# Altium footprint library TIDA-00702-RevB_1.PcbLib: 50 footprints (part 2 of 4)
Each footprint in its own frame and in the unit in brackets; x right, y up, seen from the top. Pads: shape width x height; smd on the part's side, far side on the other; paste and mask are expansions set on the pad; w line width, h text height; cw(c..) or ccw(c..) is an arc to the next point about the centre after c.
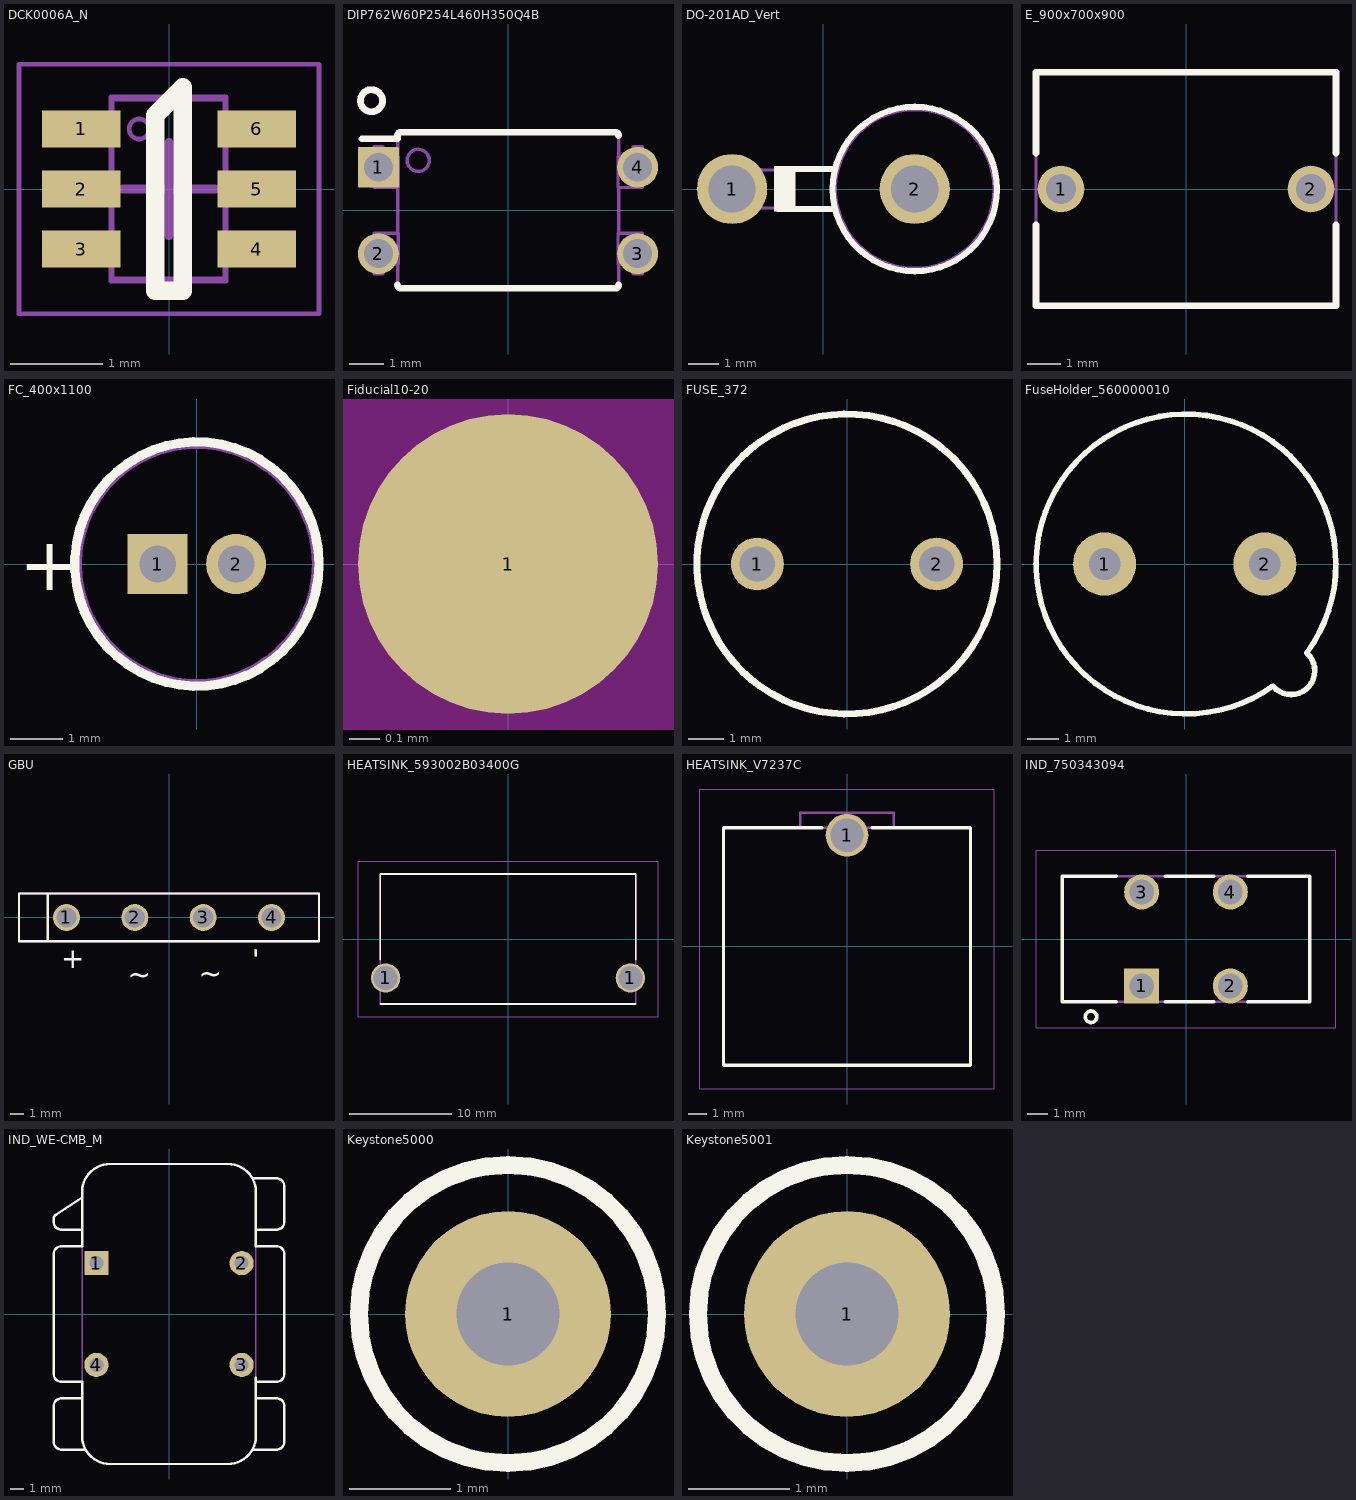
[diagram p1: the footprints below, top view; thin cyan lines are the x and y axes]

## DCK0006A_N [mm] "SOT23, 6-Leads, Body 2x1.3mm, Pitch 0.65mm, Lead Span 2.1mm, IPC Medium Density"
height 1.1
pads (6):
  rect 0.85x0.4 smd: 1(-0.95,0.65) 2(-0.95,0) 3(-0.95,-0.65) 4(0.95,-0.65) 5(0.95,0) 6(0.95,0.65)
Top Overlay:
  lines w0.2: -0.15,-1.1 -0.15,0.8 0.15,1.1 0.15,-1.1 -0.15,-1.1
Mechanical 5:
  lines w0.05: -0.613,-0.763 -0.613,-0.976 0.607,-0.976 0.607,-0.763 ; -0.613,-0.538 -0.613,-0.113 ; -0.613,0.112 -0.613,0.537 ; -0.613,0.762 -0.613,0.974 0.607,0.974 0.607,0.762 ; 0.607,-0.538 0.607,-0.113 ; 0.607,0.112 0.607,0.537 ; -0.628,-0.763 -0.628,-1.001 0.622,-1.001 0.622,-0.763 ; -0.628,-0.763 -0.853,-0.763 -0.865,-0.763 -0.959,-0.763 -1.143,-0.763 -1.143,-0.538 -0.959,-0.538 -0.865,-0.538 -0.853,-0.538 -0.628,-0.538 ; -0.628,-0.763 -0.591,-0.763 -0.591,-0.538 -0.628,-0.538 ; -0.628,-0.538 -0.628,-0.113 ; -0.628,-0.113 -0.853,-0.113 -0.865,-0.113 -0.959,-0.113 -1.143,-0.113 -1.143,0.112 -0.959,0.112 -0.865,0.112 -0.853,0.112 -0.628,0.112 ; -0.628,-0.113 -0.591,-0.113 -0.591,0.112 -0.628,0.112 ; -0.628,0.112 -0.628,0.537 ; -0.628,0.537 -0.853,0.537 -0.865,0.537 -0.959,0.537 -1.143,0.537 -1.143,0.762 -0.959,0.762 -0.865,0.762 -0.853,0.762 -0.628,0.762 ; -0.628,0.537 -0.591,0.537 -0.591,0.762 -0.628,0.762 ; -0.628,0.762 -0.628,0.999 0.622,0.999 0.622,0.762 ; 0.622,-0.763 0.847,-0.763 0.859,-0.763 0.953,-0.763 1.137,-0.763 1.137,-0.538 0.953,-0.538 0.859,-0.538 0.847,-0.538 0.622,-0.538 ; 0.622,-0.763 0.585,-0.763 0.585,-0.538 0.622,-0.538 ; 0.622,-0.538 0.622,-0.113 ; 0.622,-0.113 0.585,-0.113 0.585,0.112 0.622,0.112 ; 0.622,-0.113 0.847,-0.113 0.859,-0.113 0.953,-0.113 1.137,-0.113 1.137,0.112 0.953,0.112 0.859,0.112 0.847,0.112 0.622,0.112 ; 0.622,0.112 0.622,0.537 ; 0.622,0.537 0.847,0.537 0.859,0.537 0.953,0.537 1.137,0.537 1.137,0.762 0.953,0.762 0.859,0.762 0.847,0.762 0.622,0.762 ; 0.622,0.537 0.585,0.537 0.585,0.762 0.622,0.762 ; -0.432,0.65 cw(c-0.323,0.65) -0.215,0.65 cw(c-0.323,0.65) -0.432,0.65
  text ".Designator" at -1.524,-0.584 h0.89
Mechanical 15:
  lines w0.05: -1.625,-1.35 -1.625,1.35 1.625,1.35 1.625,-1.35 -1.625,-1.35
  lines w0.1: -0.5,0 0.5,0 ; 0,-0.5 0,0.5
3D body: height 0.94, standoff -0.01, extent -1.14,-1 1.14,1

## DIP762W60P254L460H350Q4B [mm] "LITE-ON"
height 4.5
pads (4):
  rrect8% 1.2x1.2 hole 0.85: 1(-3.81,1.27)
  round 1.2 hole 0.85: 2(-3.81,-1.27) 3(3.81,-1.27) 4(3.81,1.27)
Top Overlay:
  circle w0.2: c-4.013,3.226 r0.325
  lines w0.2: -4.293,2.108 -3.247,2.108 -3.247,2.201 cw(c-3.148,2.201) -3.148,2.3 3.154,2.3 cw(c3.154,2.201) 3.253,2.201 ; -3.247,-2.191 ccw(c-3.148,-2.192) -3.148,-2.29 3.154,-2.29 ccw(c3.154,-2.192) 3.253,-2.191
Mechanical 5:
  circle w0.1: c-2.642,1.473 r0.325
  lines w0.1: -3.677,-1.565 -3.677,-1.865 -3.937,-1.865 -3.937,-1.565 ; -3.677,1.575 -3.677,1.875 -3.937,1.875 -3.937,1.575 ; -3.247,-1.565 -3.247,-2.191 ccw(c-3.148,-2.192) -3.148,-2.29 3.154,-2.29 ccw(c3.154,-2.192) 3.253,-2.191 3.253,-1.565 ; -3.247,-0.665 -3.247,0.675 ; -3.247,1.575 -3.247,2.201 cw(c-3.148,2.201) -3.148,2.3 3.154,2.3 cw(c3.154,2.201) 3.253,2.201 3.253,1.575 ; 3.253,-0.665 3.253,0.675 ; 3.683,-1.565 3.683,-1.865 3.943,-1.865 3.943,-1.565 ; 3.683,1.575 3.683,1.875 3.943,1.875 3.943,1.575 ; -3.937,-1.565 -3.737,-1.565 -3.229,-1.565 -3.229,-0.665 -3.737,-0.665 -3.937,-0.665 -3.937,-1.565 ; -3.937,1.575 -3.737,1.575 -3.229,1.575 -3.229,0.675 -3.737,0.675 -3.937,0.675 -3.937,1.575 ; 3.943,-1.565 3.743,-1.565 3.235,-1.565 3.235,-0.665 3.743,-0.665 3.943,-0.665 3.943,-1.565 ; 3.943,1.575 3.943,0.675 3.743,0.675 3.235,0.675 3.235,1.575 3.743,1.575 3.943,1.575
  text ".Designator" at 0.406,-0.025 h0.89
3D body: height 4.3, standoff -2.7, extent -3.94,-2.295 3.94,2.295

## DO-201AD_Vert [mm] "DO-201AD VERTICAL FOOTPRINT"
height 14.5
pads (2):
  round 2.3 hole 1.55: 1(-3,0) 2(3,0)
Top Overlay:
  circle w0.2: c3,0 r2.7
  rectangle: -1.621,-0.744 -0.921,0.756
  lines w0.2: -1.5,-0.65 0.3,-0.65 ; -1.5,0.65 0.3,0.65
Mechanical 5:
  circle w0.1: c3,0 r2.6
  rectangle: -2.696,-0.655 -1.996,0.695
  lines w0.1: -3,-0.625 0.4,-0.625 ; -3,-0.6 -3,0.6 ; -2.975,0.625 0.425,0.625
  text ".Designator" at 3.277,0.127 h0.89
3D body: height 14.8, standoff -2.54, extent -3.659,-2.655 5.655,2.655

## E_900x700x900 [mm] "TH, 2- Leads, Body 9x7mm, Pin Spacing 7.5mm"
height 12
pads (2):
  round 1.4 hole 0.9: 1(-3.75,0) 2(3.75,0)
Top Overlay:
  lines w0.2: -4.5,-1.071 -4.5,-3.5 4.5,-3.5 4.5,-1.071 ; -4.5,1.071 -4.5,3.5 4.5,3.5 4.5,1.071
Mechanical 5:
  lines w0.1: -4.5,-3.5 4.5,-3.5 4.5,3.5 -4.5,3.5 -4.5,-3.5
  text ".Designator" at -1.397,-0.406 h0.89
3D body: height 0.3, standoff -2.5, extent -4.047,-0.299 -3.45,0.3
3D body: height 1.36, standoff -0.16, extent -4.047,-1.732 -3.45,0.3
3D body: height 6.12, standoff 0.81, extent -4.047,-1.732 -1.545,-1.033
3D body: height 6.12, standoff 0.81, extent 1.546,1.033 4.048,1.732
3D body: height 1.36, standoff -0.16, extent 3.45,-0.299 4.048,1.732
3D body: height 0.3, standoff -2.5, extent 3.45,-0.299 4.048,0.299
3D body: height 11.96, standoff 3, extent -4.491,-3.5 4.491,3.5

## FC_400x1100 [mm] "Panasonic"
height 12
pads (2):
  rect 1.15x1.15 hole 0.7: 1(-0.75,0)
  round 1.15 hole 0.7: 2(0.75,0)
Top Overlay:
  circle w0.18: c0,0 r2.335
  text "+" at -3.4,-0.5 h1.02
Mechanical 5:
  circle w0.1: c0,0 r2.25
  text ".Designator" at -0.483,1.168 h0.89
  text "+" at -3.4,-0.5 h0.89
3D body: height 12.01, standoff -4, extent -2.232,-2.246 2.252,2.246

## FCC_disclaimer [mm]

## Fiducial10-20 [mm]
pads (1):
  round 1 smd mask+0.5: 1(0,0)
Top Layer keep-out:
  circle w1.178: c0,0 r0.5

## FUSE_372 [mm] "LITTELFUSE"
height 8
pads (2):
  round 1.5 hole 1: 1(-2.54,0) 2(2.54,0)
Top Overlay:
  circle w0.2: c0,0 r4.25
Mechanical 5:
  circle w0.1: c0,0 r4.25
  text ".Designator" at -0.838,-0.559 h0.89
3D body: height 4, standoff -2, extent -2.837,-0.299 -2.24,0.3
3D body: height 4, standoff -2, extent 2.242,-0.299 2.84,0.299
3D body: height 8, standoff 0, extent -4.259,-4.259 4.259,4.259

## FuseHolder_560000010 [mm] "Littelfuse fuse holder TR5"
height 5.6
pads (2):
  round 2 hole 1: 1(-2.54,0) 2(2.54,0)
Top Overlay:
  lines w0.178: -4.71,-0.051 cw(c-4.212,0) -4.71,0.051 ; 4.79,-0.051 ccw(c4.292,0) 4.79,0.051 ; 2.797,-3.868 cw(c0.04,0) 3.863,-2.819 cw(c3.372,-3.386) 2.797,-3.868
Mechanical 5:
  lines w0.127: -4.71,-0.051 cw(c-4.212,0) -4.71,0.051 ; 4.79,-0.051 ccw(c4.292,0) 4.79,0.051 ; 2.797,-3.868 ccw(c3.372,-3.386) 3.863,-2.819 ccw(c0.04,0) 2.797,-3.868
  text ".Designator" at -6.807,-2.108 h0.89
3D body: height 5.6, standoff -3, extent -4.752,-4.737 4.752,4.75

## GBU [mm] "Comchip / Diodes Inc diode bridge"
height 21.55
pads (4):
  round 2 hole 1.5: 1(-7.62,0) 2(-2.54,0) 3(2.54,0) 4(7.62,0)
Top Overlay:
  lines w0.178: -9,-1.78 -9,1.78 ; -11.15,-1.78 0,-1.78 11.15,-1.78 11.15,0 11.15,1.78 0,1.78 -11.15,1.78 -11.15,0 -11.15,-1.78
  text "~" at 2.21,-4.877 h1.52
  text "~" at -3.073,-4.978 h1.52
  text "-" at 7.061,-3.048 h1.52
  text "+" at -8.026,-3.759 h1.52
Mechanical 5:
  lines w0.127: -9,-1.78 -9,1.78 ; -11.15,-1.78 0,-1.78 11.15,-1.78 11.15,0 11.15,1.78 0,1.78 -11.15,1.78 -11.15,0 -11.15,-1.78
  text "~" at 2.311,-3.226 h0.89
  text "~" at -1.676,-3.277 h0.89
  text "-" at 7.061,-2.591 h0.89
  text "+" at -7.823,-2.972 h0.89
  text ".Designator" at -0.787,1.041 h0.89
3D body: height 21.55, standoff -15.25, extent -11.15,-1.76 11.15,1.8

## HEATSINK_593002B03400G [mm] "HEATSINK, 25X12.7X29.97 MM"
height 29.97
pads (2):
  round 2.868 hole 2.36: 1(-11.965,-3.81) 1(11.965,-3.81)
Top Overlay:
  lines w0.178: -12.5,-6.35 12.5,-6.35 ; -12.5,-2 -12.5,6.35 12.5,6.35 12.5,-2
  text ".Designator" at -13.843,3.099 h0.89
Mechanical 5:
  lines w0.127: -12.5,-6.35 12.5,-6.35 12.5,6.35 -12.5,6.35 -12.5,-6.35
  text ".Designator" at 12.979,7.112 h0.89
Mechanical 15:
  lines w0.05: -14.669,-7.62 14.669,-7.62 14.669,7.62 -14.669,7.62 -14.669,-7.62
Mechanical 17:
  text "LEAD LENGTH: 4.27 MM" at -9.652,2.286 h1
3D body: height 29.97, standoff 0, extent -12.5,-6.35 12.5,6.35

## HEATSINK_V7237C [mm] "HEATSINK,TO-220,13.21X12.7MM"
height 19.05
pads (1):
  round 2.28 hole 1.78: 1(0,5.95)
Top Overlay:
  lines w0.178: -1.342,6.35 -6.605,6.35 -6.605,-6.35 6.605,-6.35 6.605,6.35 1.342,6.35
  text ".Designator" at -2.87,-7.569 h0.89
Mechanical 5:
  lines w0.127: -2.5,6.35 -2.5,7.15 2.5,7.15 2.5,6.35 ; -6.605,-6.35 6.605,-6.35 6.605,6.35 -6.605,6.35 -6.605,-6.35
  text ".Designator" at -6.248,6.756 h0.89
Mechanical 15:
  lines w0.05: -7.875,-7.62 7.875,-7.62 7.875,8.42 -7.875,8.42 -7.875,-7.62
Mechanical 17:
  text "LEAD LENGTH: 6.35 MM" at -9.169,-2.515 h1
3D body: height 19.05, standoff 0, extent -6.605,-6.35 6.605,6.35

## IND_750343094 [mm] "INDUCTOR, TH-4P"
height 13.06
pads (4):
  rect 1.7x1.7 / inner round 1.7 / far side rect 1.7x1.7 hole 1.2: 1(-2.16,-2.285)
  round 1.7 hole 1.2: 2(2.16,-2.285) 3(-2.16,2.285) 4(2.16,2.285)
Top Overlay:
  circle w0.178: c-4.623,-3.785 r0.279
  lines w0.178: -3.4,-3.05 -6.03,-3.05 -6.03,3.05 -3.4,3.05 ; -1,-3.05 1.35,-3.05 ; -1,3.05 1.35,3.05 ; 3,-3.05 6.03,-3.05 6.03,3.05 3,3.05
Bottom Overlay:
  lines w0.178: -6.03,-3.048 -5.302,-3.048 ; -6.03,-1.966 -6.03,-0.95 ; -6.03,0.034 -6.03,1.05 ; -6.03,2.034 -6.03,3.05 -4.887,3.05 ; -4.445,-3.048 -3.302,-3.048 ; -4.03,3.05 -2.92,3.05 ; -1.35,3.05 1.27,3.048 ; -1,-3.05 1.35,-3.05 ; 2.92,-3.05 4.03,-3.05 ; 3.175,3.048 4.445,3.048 ; 4.887,-3.05 6.03,-3.05 6.03,-2.034 ; 5.302,3.048 6.03,3.048 ; 6.03,-1.05 6.03,-0.034 ; 6.03,0.95 6.03,1.966
Mechanical 5:
  circle w0.127: c-2.16,-2.285 r0.279
  lines w0.127: -6.03,-3.05 6.03,-3.05 6.03,3.05 -6.03,3.05 -6.03,-3.05
  text ".Designator" at -1.524,-0.508 h0.89
Mechanical 15:
  lines w0.05: -7.3,-4.32 7.3,-4.32 7.3,4.32 -7.3,4.32 -7.3,-4.32
Mechanical 17:
  text "LEAD LENGHT: 2.81MM" at -13.843,-6.604 h1.52
3D body: height 13.06, standoff 0, extent -6.03,-3.05 6.03,3.05

## IND_WE-CMB_M [mil] "Wurth"
height 1102.36
pads (4):
  rect 70x70 hole 40: 1(-210.63,147.64)
  round 70 hole 40: 2(210.63,147.64) 3(210.63,-147.64) 4(-210.63,-147.64)
Top Overlay:
  lines w7: -251.97,-354.33 ccw(c-171.26,-354.33) -171.26,-435.04 171.26,-435.04 ccw(c171.26,-354.33) 251.97,-354.33 251.97,-346.59 251.97,-323.7 251.97,-286.66 251.97,-237.09 251.97,-184.41 ; -251.97,-354.08 -251.97,-349.11 -251.97,-328.88 -251.97,-294.28 -251.97,-246.81 -251.97,-206.08 -251.97,-203.51 -251.97,-198.82 ; -251.97,-244.09 -311.02,-244.09 ccw(c-311.02,-267.72) -334.65,-267.72 -334.65,-370.08 ccw(c-311.02,-370.08) -311.02,-393.7 -241.67,-393.7 ; -251.97,-196.85 -311.02,-196.85 cw(c-311.02,-173.23) -334.65,-173.23 -334.65,173.23 cw(c-311.02,173.23) -311.02,196.85 -251.97,196.85 ; -251.97,198.82 -251.97,203.51 -251.97,206.08 -251.97,246.81 -251.97,294.28 -251.97,328.88 -251.97,349.11 -251.97,354.08 ; -251.97,244.09 -311.02,244.09 cw(c-311.02,267.72) -334.65,267.72 -334.65,274.98 cw(c-318.9,274.98) -327.56,288.13 -251.97,337.93 ; -251.97,354.33 cw(c-171.26,354.33) -171.26,435.04 171.26,435.04 cw(c171.26,354.33) 251.97,354.33 251.97,346.59 251.97,323.7 251.97,286.66 251.97,196.85 311.02,196.85 cw(c311.02,173.23) 334.65,173.23 334.65,-173.23 cw(c311.02,-173.23) 311.02,-196.85 251.97,-196.85 ; 241.71,-393.7 311.02,-393.7 ccw(c311.02,-370.08) 334.65,-370.08 334.65,-267.72 ccw(c311.02,-267.72) 311.02,-244.09 251.97,-244.09 ; 241.71,393.7 311.02,393.7 cw(c311.02,370.08) 334.65,370.08 334.65,267.72 cw(c311.02,267.72) 311.02,244.09 251.97,244.09
Mechanical 5:
  lines w5: -251.97,-354.33 ccw(c-171.26,-354.33) -171.26,-435.04 171.26,-435.04 ccw(c171.26,-354.33) 251.97,-354.33 251.97,-346.59 251.97,-323.7 251.97,-286.66 251.97,-237.09 251.97,-184.41 251.97,-165.23 251.97,237.09 251.97,286.66 251.97,323.7 251.97,346.59 251.97,354.33 ccw(c171.26,354.33) 171.26,435.04 -171.26,435.04 ccw(c-171.26,354.33) -251.97,354.33 ; -251.97,-354.08 -251.97,-349.11 -251.97,-328.88 -251.97,-294.28 -251.97,-246.81 -251.97,-206.08 -251.97,-203.51 -251.97,-198.82 -251.97,-165.23 -251.97,198.82 -251.97,203.51 -251.97,206.08 -251.97,246.81 -251.97,294.28 -251.97,328.88 -251.97,349.11 -251.97,354.08 ; -251.97,-244.09 -311.02,-244.09 ccw(c-311.02,-267.72) -334.65,-267.72 -334.65,-370.08 ccw(c-311.02,-370.08) -311.02,-393.7 -241.67,-393.7 ; -251.97,-196.85 -311.02,-196.85 cw(c-311.02,-173.23) -334.65,-173.23 -334.65,173.23 cw(c-311.02,173.23) -311.02,196.85 -251.97,196.85 ; -251.97,244.09 -311.02,244.09 cw(c-311.02,267.72) -334.65,267.72 -334.65,274.98 cw(c-318.9,274.98) -327.56,288.13 -251.97,337.93 ; 241.71,-393.7 311.02,-393.7 ccw(c311.02,-370.08) 334.65,-370.08 334.65,-267.72 ccw(c311.02,-267.72) 311.02,-244.09 251.97,-244.09 ; 241.71,393.7 311.02,393.7 cw(c311.02,370.08) 334.65,370.08 334.65,267.72 cw(c311.02,267.72) 311.02,244.09 251.97,244.09 ; 251.97,-196.85 311.02,-196.85 ccw(c311.02,-173.23) 334.65,-173.23 334.65,173.23 ccw(c311.02,173.23) 311.02,196.85 251.97,196.85
  text ".Designator" at 6,21 h35
3D body: height 1043.91, standoff -117.51, extent -334.65,-393.69 334.64,393.71

## Keystone5000 [mil] "For Keystone 500x miniature loop terminals"
height 181.1
pads (1):
  round 80 hole 40: 1(0,0)
Top Overlay:
  circle w7: c0,0 r58
Mechanical 5:
  circle w5: c0,0 r58.31
  text ".Designator" at -41,73 h35
3D body: height 181.97, standoff -118.11, extent -49,-49 49.04,49.24

## Keystone5001 [mil] "For Keystone 500x miniature loop terminals"
height 181.1
pads (1):
  round 80 hole 40: 1(0,0)
Top Overlay:
  circle w7: c0,0 r58
Mechanical 5:
  circle w5: c0,0 r58.31
  text ".Designator" at -27,71 h35
3D body: height 181.97, standoff -118.11, extent -49,-49 49.04,49.24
